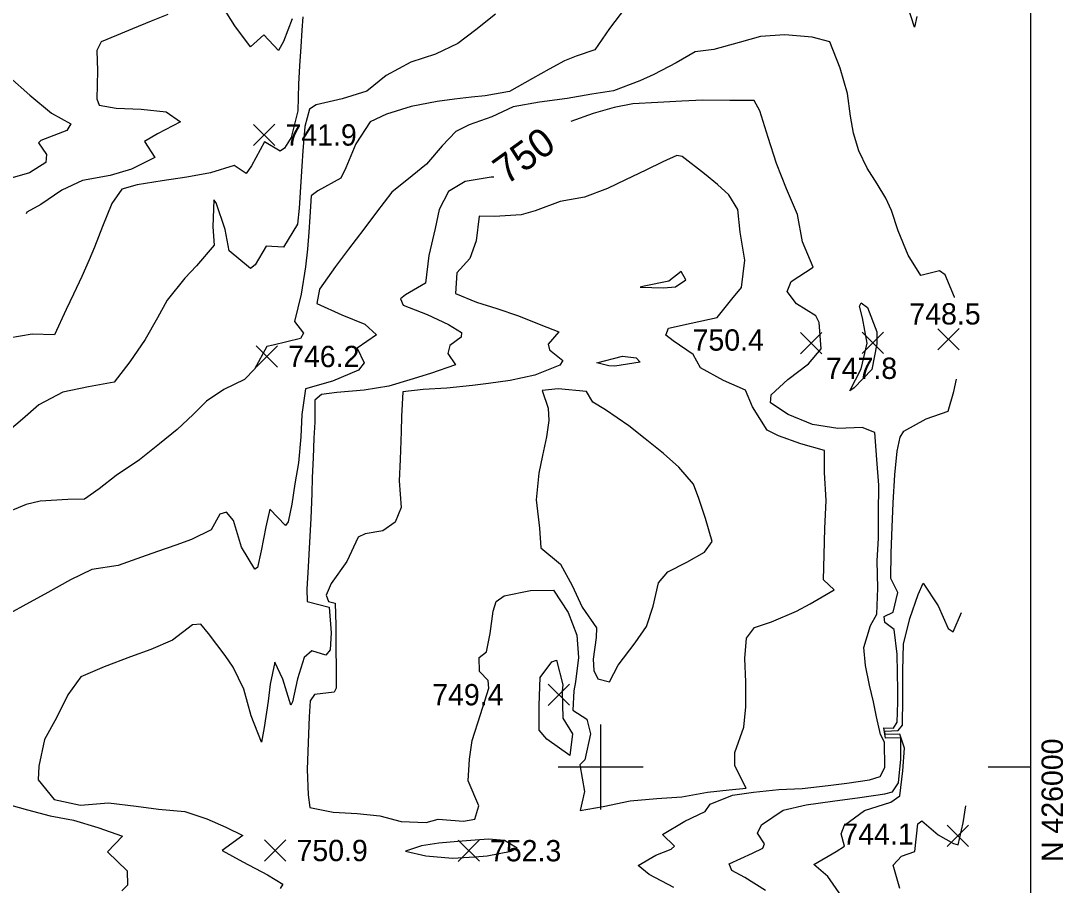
# Model space of a CAD drawing. Extents: x 2566079 to 2571326, y 424054 to 426896.
# Drawn here: x 2570592 to 2571326, y 425917 to 426525 of the extents above; entities that cross this region are included whole.
import ezdxf

# ---------------------------------------------------------------- set-up
doc = ezdxf.new("R2010")
doc.units = 0
for name, color, linetype in [('Contour_ADS_Label_Major', 7, 'Continuous'), ('Contour_ADS_Major', 7, 'Continuous'), ('Contour_ADS_Minor', 7, 'Continuous'), ('Contour_ADS_Spot_Elevation', 7, 'Continuous'), ('Contour_ADS_State_Plane_Border', 7, 'Continuous'), ('Contour_ADS_Tick', 7, 'Continuous')]:
    doc.layers.add(name, color=color, linetype=linetype)

# ---------------------------------------------------------------- blocks, each defined once
blk = doc.blocks.new('S890')
at = {"layer": 'Contour_ADS_Tick'}
for p, q in [((0, -0.5), (0, 0.5)), ((-0.5, 0), (0.5, 0))]:
    blk.add_line(p, q, dxfattribs=at)
blk = doc.blocks.new('S750')
at = {"layer": 'Contour_ADS_Spot_Elevation'}
for p, q in [((-0.5, 0.498), (0.5, -0.498)), ((-0.498, -0.5), (0.498, 0.5))]:
    blk.add_line(p, q, dxfattribs=at)

msp = doc.modelspace()

# ---------------------------------------------------------------- linework, layer by layer
at = {"layer": 'Contour_ADS_Major'}
for points in [[(2570782.76, 426526.65), (2570776.66, 426510.83), (2570773.09, 426504.52), (2570762.75, 426515.5), (2570753.38, 426507.1), (2570742.29, 426521.75), (2570733.83, 426535.09)], [(2570695.09, 426529.67), (2570683.51, 426525.15), (2570670.35, 426519.79), (2570658.94, 426515.1), (2570648.23, 426510.46), (2570645.12, 426504.44), (2570645.77, 426490.18), (2570645.24, 426470.46), (2570646.88, 426465.87), (2570658.86, 426463.87), (2570676.46, 426463.07), (2570694.14, 426461.19), (2570704.09, 426454.15), (2570687.89, 426445.78), (2570678.85, 426440.38), (2570685.97, 426429.12), (2570669.52, 426420.91), (2570654.64, 426416.42), (2570635.19, 426412.92), (2570620.56, 426406.1), (2570605.87, 426395.97), (2570596.02, 426390.51), (2570595.55, 426389.36)], [(2571051.6, 425915.17), (2571034.16, 425924.26), (2571026.36, 425930.55), (2571038.78, 425937.83), (2571049.65, 425942.08), (2571052.04, 425944.33), (2571043.44, 425952.53), (2571059.36, 425961.78), (2571073.47, 425968.77), (2571077.12, 425973.74), (2571092.72, 425980.08), (2571107.51, 425982.25), (2571125.37, 425984.19), (2571141.98, 425984.93), (2571160.28, 425987.07), (2571173.21, 425988.59), (2571189.28, 425990.87), (2571196.76, 425993.24), (2571200.18, 425999.75), (2571199.8, 426017.53), (2571196.99, 426022.9), (2571194.19, 426035.37), (2571192.09, 426045.89), (2571189.29, 426057.52), (2571186.46, 426071.38), (2571185.27, 426084.2), (2571189.98, 426099.65), (2571194.38, 426107.6), (2571195.25, 426125.81), (2571194.64, 426145.24), (2571195.65, 426161.18), (2571195.67, 426178.45), (2571195.74, 426198.39), (2571194.38, 426216.45), (2571193.02, 426235.56), (2571184.03, 426238.94), (2571167.1, 426238.23), (2571149.22, 426241.02), (2571131.92, 426248.06), (2571119.65, 426256.38), (2571120.12, 426261.9), (2571131.85, 426272.85), (2571146.25, 426283.74), (2571155.15, 426294.39), (2571153.88, 426312.95), (2571151.6, 426317.64), (2571137.84, 426326.11), (2571131.4, 426334.71), (2571134.22, 426341.81), (2571149.52, 426351.81), (2571142.22, 426369.66), (2571138.64, 426388.88), (2571130.8, 426407.11), (2571123.91, 426424.93), (2571117.89, 426443.25), (2571112.17, 426462.02), (2571108.16, 426469.25), (2571090.93, 426469.13), (2571071.9, 426469.49), (2571057.12, 426468.79), (2571040.22, 426467.86), (2571022.65, 426466.82), (2571009.53, 426464.24), (2570994.74, 426460.03), (2570978.91, 426454.36)], [(2570924.84, 426415.36), (2570922.78, 426415.18), (2570904.52, 426412.1), (2570892.78, 426405.05), (2570886.27, 426392.38), (2570883.41, 426379.18), (2570879.07, 426360.05), (2570876.58, 426340.56), (2570862.46, 426332.3), (2570858.98, 426329.62), (2570860.99, 426325.22), (2570877.89, 426318.48), (2570892.88, 426311.61), (2570901.88, 426305.82), (2570901.66, 426302.57), (2570893.7, 426296.83), (2570892.41, 426291.05), (2570897.78, 426283.18), (2570880.06, 426277.14), (2570865.66, 426272.48), (2570850.73, 426268.07), (2570833.46, 426265.38), (2570814.22, 426263.71), (2570803.35, 426262.18), (2570798.79, 426258.31), (2570798.63, 426242.7), (2570798.09, 426231.54), (2570797.48, 426217.59), (2570796.92, 426203.79), (2570796.49, 426192.44), (2570795.82, 426174.88), (2570795.02, 426158.38), (2570794.02, 426140.86), (2570793.08, 426125.22), (2570793.23, 426116.5), (2570808.86, 426112.62), (2570810.31, 426094.51), (2570809.4, 426082.49), (2570806.36, 426078.71), (2570796.56, 426081.72), (2570791.2, 426076.99), (2570786.5, 426062.05), (2570783.05, 426045.89), (2570781.82, 426043.62), (2570776.21, 426061.9), (2570770.64, 426073.83), (2570767.22, 426058.39), (2570765.91, 426046.23), (2570763.1, 426027.81), (2570761.07, 426017.59), (2570753.83, 426035.97), (2570748.75, 426054.71), (2570741.21, 426070.2), (2570735.57, 426078.48), (2570723.9, 426094.04), (2570718.33, 426100.55), (2570712.58, 426100.01), (2570698.39, 426089.2), (2570683.29, 426082.68), (2570669.02, 426077.61), (2570650.4, 426070.61), (2570634.04, 426063.51), (2570624.67, 426050.75), (2570616.79, 426034.61), (2570608.34, 426019.25), (2570604.29, 426000.67), (2570603.86, 425990.86), (2570615.19, 425977.08), (2570633.81, 425973.06), (2570653.44, 425974.75), (2570672.98, 425972.49), (2570688.58, 425970.4), (2570707.12, 425968.58), (2570722.75, 425963.42), (2570735.96, 425957.56), (2570748.09, 425951.84), (2570733.53, 425941.11), (2570748.12, 425933.15), (2570765.39, 425923.98), (2570776.12, 425917.51), (2570774.38, 425914.39)]]:
    msp.add_lwpolyline(points, dxfattribs=at)
msp.add_lwpolyline([(2570972.89, 426053.35), (2570973.37, 426034.49), (2570980.26, 426023.42), (2570978.35, 426008.05), (2570962.11, 426019.7), (2570956.59, 426025.91), (2570956.58, 426043.56), (2570957.42, 426063), (2570965.68, 426074.13), (2570968.8, 426075.24), (2570973.35, 426057.9), (2570972.89, 426053.35)], close=True, dxfattribs=at)
at = {"layer": 'Contour_ADS_Minor'}
for points in [[(2571017.39, 426534.66), (2571006.21, 426519.91), (2570995.86, 426504.93), (2570982.72, 426500.39), (2570974.52, 426497.1), (2570963.61, 426491.38), (2570951.97, 426484.7), (2570935.84, 426475.64), (2570918.68, 426472.53), (2570908.95, 426471.55), (2570896.98, 426470.2), (2570884.93, 426468.55), (2570866.62, 426464.95), (2570849.19, 426459.5), (2570837.71, 426454.09), (2570827.61, 426438.69), (2570820.45, 426421.83), (2570817.08, 426414.49), (2570800.88, 426405.59), (2570796.23, 426402.09), (2570795.29, 426387.24), (2570794.54, 426376.57), (2570793.46, 426364.47), (2570792.04, 426352.23), (2570789.19, 426332.82), (2570784.32, 426313.64), (2570790.75, 426305.38), (2570788.58, 426301.68), (2570769.33, 426297.09), (2570764.81, 426295.92), (2570756.2, 426280.08), (2570749.26, 426272.73), (2570734.64, 426265.81), (2570722.43, 426257.59), (2570713.06, 426248.12), (2570701.69, 426237.52), (2570689.42, 426227.55), (2570675.29, 426216.35), (2570658.77, 426205.18), (2570646.92, 426195.88), (2570636.43, 426188.62), (2570624.77, 426188.37), (2570605.41, 426187.26), (2570595.34, 426184.73), (2570577.27, 426177.28)], [(2571222.61, 426528.34), (2571220.86, 426520.88), (2571216.55, 426534.81)], [(2570926, 426530.03), (2570912.13, 426519.08), (2570899.46, 426509.41), (2570883.64, 426501.77), (2570866.31, 426496.16), (2570848.93, 426486.81), (2570835.22, 426475.85), (2570818.07, 426470.32), (2570799.76, 426466.16), (2570794.9, 426463.14), (2570791.64, 426450.89), (2570790.31, 426433.89), (2570789.55, 426422.94), (2570788.79, 426411.99), (2570787.62, 426393.39), (2570786.4, 426382.19), (2570776.72, 426365.95), (2570764.44, 426366.61), (2570756.75, 426353.48), (2570753.48, 426350.86), (2570738.43, 426363.33), (2570735.48, 426378.45), (2570729.27, 426397.09), (2570727.55, 426399.32), (2570726.96, 426380.27), (2570727.79, 426367.3), (2570715.35, 426352.76), (2570707.24, 426344.07), (2570694.77, 426328.63), (2570687.92, 426316.28), (2570679.2, 426301.08), (2570668.38, 426285.35), (2570657.47, 426270.83), (2570639.29, 426267.7), (2570621.21, 426263.9), (2570604.42, 426255.02), (2570592.77, 426244.77), (2570578.85, 426232.9)], [(2570790.31, 426528.19), (2570789.62, 426518.74), (2570788.8, 426506.98), (2570787.91, 426493.69), (2570787.13, 426480.81), (2570786.76, 426461.89), (2570782.07, 426443.27), (2570777.42, 426435.73), (2570774.4, 426433.47), (2570763.3, 426440.07), (2570754.1, 426423.23), (2570750.42, 426417.77), (2570741.96, 426423.38), (2570725.21, 426418.23), (2570708.67, 426415.32), (2570691.11, 426412.76), (2570673.54, 426409.91), (2570662.91, 426406.89), (2570655.7, 426396.62), (2570649.15, 426380.42), (2570643.63, 426365.92), (2570639.8, 426356.94), (2570634.55, 426345.38), (2570628.76, 426332.96), (2570623.65, 426322.06), (2570615.44, 426304.26), (2570599.72, 426304.69), (2570583.2, 426301.98)], [(2571249.23, 426330.42), (2571249.16, 426330.65), (2571242.57, 426346.48), (2571238.53, 426349.27), (2571225.32, 426346.03), (2571216.53, 426360.38), (2571209.38, 426377.55), (2571204.84, 426391.72), (2571200.76, 426400.41), (2571194.63, 426410.45), (2571187.71, 426421.66), (2571181.7, 426433.77), (2571177.9, 426446.32), (2571175.87, 426458.09), (2571173.82, 426474.17), (2571168.52, 426492.04), (2571161.43, 426510.64), (2571148.84, 426513.76), (2571129.75, 426515.5), (2571112.49, 426514.39), (2571097.43, 426510.09), (2571079.6, 426505.11), (2571066.63, 426503.57), (2571053.15, 426495.74), (2571037.42, 426487.63), (2571027.65, 426482.97), (2571008.95, 426476.03), (2570993.73, 426473.62), (2570976.33, 426470.67), (2570956.8, 426468.02), (2570938.28, 426464.82), (2570923.29, 426457.82), (2570907.48, 426452.16), (2570898, 426447.35), (2570888.38, 426437.27), (2570877.34, 426424.49), (2570867.22, 426416.22), (2570852.89, 426404.62), (2570842.17, 426390.68), (2570833.11, 426378.71), (2570822.51, 426364.61), (2570813.18, 426352.24), (2570801.91, 426336.42), (2570800.21, 426326.3), (2570817.81, 426318.38), (2570833.93, 426311.85), (2570842.12, 426304.25), (2570828.5, 426294.83), (2570833.43, 426284.64), (2570829.56, 426279.34), (2570811.2, 426271.67), (2570792.17, 426266.23), (2570789.6, 426248.05), (2570788.96, 426232.36), (2570787.22, 426214.19), (2570784.69, 426199.43), (2570782.41, 426185.05), (2570780.02, 426172.55), (2570778.01, 426170.04), (2570767.01, 426181.49), (2570764.27, 426169.02), (2570760.87, 426152.26), (2570758.28, 426140.56), (2570756.51, 426139.24), (2570747.14, 426154.75), (2570741.37, 426173.45), (2570736.51, 426179.44), (2570731.92, 426178.04), (2570725.68, 426166.88), (2570711.96, 426160.07), (2570700.76, 426156.15), (2570687.96, 426151.73), (2570676.55, 426147.72), (2570660.16, 426141.82), (2570641.61, 426138.95), (2570626.63, 426131.78), (2570618.68, 426127.26), (2570608.57, 426121.73), (2570597.83, 426115.92), (2570581.64, 426106.79)], [(2570583.62, 426485.61), (2570597.95, 426473.04), (2570613.36, 426460.35), (2570627, 426452.72), (2570624.03, 426448), (2570605.71, 426441.02), (2570604.17, 426439.32), (2570609.67, 426431.09), (2570609.2, 426425.68), (2570597.82, 426418.23), (2570585.65, 426414.87)], [(2570980.97, 426053.57), (2570980.31, 426040.07), (2570990.3, 426033.77), (2570992.74, 426023.32), (2570988.79, 426004.93), (2570985.31, 426001.41), (2570988.65, 425982.64), (2570985.61, 425969.3), (2571001.69, 425972.15), (2571020.81, 425976.18), (2571039.47, 425977.77), (2571057.19, 425979.01), (2571075.18, 425982.21), (2571090.42, 425983.93), (2571102.43, 425985), (2571094.39, 426000.92), (2571094.52, 426010.1), (2571100.78, 426028.13), (2571102.21, 426042.24), (2571102.2, 426059.88), (2571101.52, 426076.47), (2571102.72, 426090.69), (2571108.35, 426098.26), (2571120.28, 426102.26), (2571137.99, 426109.6), (2571147.46, 426114.78), (2571164.36, 426124.84), (2571156.84, 426131.68), (2571157.42, 426149.46), (2571157.94, 426167.97), (2571158.77, 426187.66), (2571157.55, 426207.31), (2571157.58, 426222.82), (2571140.87, 426227.46), (2571125.18, 426233.1), (2571117.22, 426237.06), (2571106.96, 426253.55), (2571102.03, 426265.3), (2571086.52, 426272.18), (2571070.21, 426281.06), (2571065.02, 426290.46), (2571051.09, 426300.11), (2571045.98, 426303.95), (2571047.69, 426308.83), (2571063.61, 426312.56), (2571082.02, 426316.43), (2571092.35, 426329.41), (2571099.08, 426337.66), (2571101.4, 426356.88), (2571098.15, 426376.57), (2571096.63, 426392.52), (2571090.32, 426402.78), (2571082.35, 426410.03), (2571072.98, 426417.53), (2571057.4, 426429.69), (2571053.51, 426430.5), (2571043.76, 426426.03), (2571031.71, 426420.23), (2571017.46, 426413.34), (2571004.9, 426407.32), (2570988.63, 426401.27), (2570971.35, 426398.11), (2570953.9, 426391.52), (2570944.11, 426388.79), (2570925.23, 426387.65), (2570914.47, 426387.68), (2570912.28, 426370.51), (2570907.93, 426357.93), (2570898.8, 426347.96), (2570897.71, 426333.41), (2570912.47, 426327.32), (2570926.84, 426322.8), (2570942.19, 426317.57), (2570957.9, 426311.27), (2570970.47, 426306.3), (2570963.06, 426297.7), (2570963.91, 426293.69), (2570973.24, 426286.19), (2570971.27, 426282.86), (2570953.73, 426275.9), (2570936.23, 426272.01), (2570921.01, 426270.04), (2570909.71, 426268.64), (2570891.57, 426266.8), (2570875.03, 426265.8), (2570860.7, 426264.06), (2570859.66, 426246.64), (2570859.48, 426236.3), (2570858.72, 426216.41), (2570858.14, 426201.56), (2570859.54, 426182.65), (2570855.35, 426172.26), (2570846.53, 426166.3), (2570834.24, 426164.09), (2570829.14, 426161.8), (2570821.27, 426144.68), (2570810.2, 426129.29), (2570806.71, 426120.96), (2570808.31, 426116.45), (2570812.98, 426115.31), (2570813.46, 426099.8)], [(2571229.22, 426245.19), (2571244.77, 426250.62), (2571248.58, 426264.29), (2571250.5, 426273.03)], [(2571116.02, 425913.13), (2571101.47, 425922.15), (2571092.35, 425927.09), (2571090.39, 425931.75), (2571106.8, 425939.45), (2571114.09, 425942.96), (2571115.4, 425946.01), (2571110.5, 425953.45), (2571113.29, 425959.25), (2571128.38, 425969.66), (2571144.62, 425973.27), (2571163.29, 425975.88), (2571182.43, 425978.44), (2571200.09, 425981.11), (2571205.57, 425982.6), (2571209.78, 425988.79), (2571211.32, 426005.48), (2571211.38, 426020.49), (2571200.49, 426020.41), (2571199.47, 426027.47), (2571206.24, 426027.35), (2571208.74, 426031.52), (2571209.15, 426045.65), (2571209.12, 426054.15), (2571209.09, 426066.24), (2571208.84, 426079.4), (2571206.63, 426096.8), (2571200.06, 426101.7), (2571199.59, 426105.95), (2571206.05, 426108.98), (2571209.29, 426122.76), (2571204.28, 426132.64), (2571204.53, 426150.79), (2571205.15, 426168.89), (2571205.96, 426186.01), (2571207.18, 426205.65), (2571208.84, 426222.4), (2571210.94, 426232.22), (2571213.39, 426236.54), (2571229.22, 426245.19)], [(2571169.6, 425909.12), (2571159.94, 425923), (2571149.99, 425931.28), (2571165.83, 425940.6), (2571171.69, 425944.32), (2571169.35, 425952.85), (2571171.62, 425959.06), (2571185.7, 425969.49), (2571204.23, 425975.14), (2571210.61, 425979.73), (2571212.87, 425997.4), (2571213.89, 426013.17), (2571210.56, 426023.16), (2571200.34, 426022.77), (2571200.1, 426025.16), (2571209.38, 426025.79), (2571212.5, 426029.49), (2571212.7, 426048.57), (2571212.76, 426067.99), (2571213.32, 426086.56), (2571217.68, 426104.61), (2571223.57, 426121.47), (2571227.16, 426129.33), (2571237.53, 426113.43), (2571244.66, 426097.6), (2571248.12, 426095.13), (2571254.16, 426108.85)], [(2570813.46, 426099.8), (2570813.51, 426085.85), (2570813.75, 426067.24), (2570813.74, 426055.44), (2570812.23, 426052.65), (2570798.51, 426051.05), (2570795.31, 426046.66), (2570794.72, 426035.37), (2570793.93, 426017.34), (2570793.27, 425998.21), (2570793.96, 425980.39), (2570795.19, 425971.54), (2570811.71, 425968.14), (2570828.59, 425967.37), (2570844.49, 425965.53), (2570859.4, 425961.6), (2570877.22, 425960.87), (2570885.56, 425963.37), (2570903.36, 425961.77), (2570911.28, 425963.22), (2570914.18, 425972.62), (2570906.75, 425990.17), (2570907.63, 426005.4), (2570909.55, 426018.58), (2570915.45, 426036.93), (2570921.25, 426055.43), (2570920.77, 426060.88), (2570914.67, 426067.25), (2570914.32, 426077.15), (2570919.56, 426081.17), (2570922.11, 426093.88), (2570924.33, 426109.63), (2570926.51, 426116.6), (2570932.05, 426120.5), (2570950.63, 426124.21), (2570966.8, 426124.41), (2570977.07, 426108.82), (2570983.22, 426092.91), (2570984.34, 426077), (2570982.22, 426059.92), (2570980.97, 426053.57), (2570980.97, 426053.57)], [(2570578.67, 425974.69), (2570596.34, 425969.84), (2570612.26, 425965.68), (2570628.87, 425962.64), (2570645.86, 425957.34), (2570663.33, 425951.38), (2570652.71, 425940.3)], [(2571210.63, 425914.52), (2571206.01, 425930.8), (2571211.89, 425937.13), (2571221.19, 425940.41), (2571223.31, 425960.03), (2571226.02, 425962.14), (2571237.58, 425952.14), (2571248.48, 425946.04), (2571251.63, 425945.2), (2571255.12, 425960.6), (2571257.19, 425972.74)], [(2570652.71, 425940.3), (2570666.49, 425926.83), (2570666.74, 425916.92), (2570662.82, 425912.83)]]:
    msp.add_lwpolyline(points, dxfattribs=at)
for points in [[(2571059.88, 426342.87), (2571056.64, 426348.74), (2571047.89, 426342.05), (2571030.53, 426338.49), (2571027.77, 426337.71), (2571044.3, 426337.36), (2571052.64, 426337.93), (2571059.88, 426342.87)], [(2571194.56, 426297.89), (2571190.93, 426279.92), (2571178.44, 426266.85), (2571175.43, 426264.91), (2571183.33, 426280.23), (2571187.69, 426298.47), (2571184.32, 426316.16), (2571182.17, 426324.38), (2571183.34, 426326.69), (2571187.8, 426323.6), (2571194.46, 426306.34), (2571194.56, 426297.89)], [(2571005.68, 426282.46), (2570997.26, 426284.62), (2571015.26, 426289.2), (2571024.93, 426288.12), (2571027.81, 426284.97), (2571010.07, 426282.08), (2571005.68, 426282.46)], [(2570996.8, 426091.28), (2570994.61, 426075.9), (2570995.17, 426067.89), (2570997.92, 426062), (2571006.12, 426059.96), (2571012.22, 426071.61), (2571024.2, 426087.39), (2571032.28, 426098.86), (2571036.94, 426113.24), (2571040.71, 426129.66), (2571047.23, 426137.4), (2571060.7, 426144.28), (2571073.03, 426151.28), (2571078.47, 426158.75), (2571073.85, 426174.9), (2571069.2, 426189.06), (2571065.33, 426199.05), (2571055.11, 426211.15), (2571044.19, 426220.67), (2571031.41, 426231.08), (2571019.9, 426240.08), (2571003.42, 426251.39), (2570994.43, 426256.89), (2570989.99, 426264.43), (2570970.16, 426266.2), (2570958.86, 426265.13), (2570963.1, 426252.72), (2570963.49, 426244), (2570961.82, 426232.37), (2570959, 426219.36), (2570956.35, 426206.92), (2570954.59, 426188.05), (2570956.86, 426168.2), (2570957.78, 426154.4), (2570971.6, 426142.71), (2570979.9, 426127.76), (2570987, 426112.42), (2570997.12, 426097.98), (2570996.8, 426091.28)], [(2570919.96, 425937.56), (2570936.96, 425940.74), (2570941.23, 425942.78), (2570932.24, 425948.31), (2570921.09, 425949.1), (2570911.66, 425948.51), (2570899.36, 425947.57), (2570886.07, 425946.26), (2570873.82, 425944.57), (2570862.55, 425940.71), (2570876.93, 425937.39), (2570895.54, 425935.72), (2570911.46, 425936.66), (2570919.96, 425937.56)]]:
    msp.add_lwpolyline(points, close=True, dxfattribs=at)
at = {"layer": 'Contour_ADS_State_Plane_Border'}
msp.add_line((2571272.93, 426000), (2571302.93, 426000), dxfattribs=at)
msp.add_lwpolyline([(2566079.33, 424077.11), (2571302.93, 424077.11), (2571302.93, 426873.74), (2566079.33, 426873.74), (2566079.33, 424077.11)], close=True, dxfattribs=at)

# ---------------------------------------------------------------- block references
at = {"layer": 'Contour_ADS_Spot_Elevation', "xscale": 15, "yscale": 15}
for p in [(2570763.03, 426444.96), (2571148.21, 426298.37), (2571191.67, 426298.61), (2571244.88, 426301.11), (2570764.9, 426289.02), (2570970.47, 426050.89), (2571251.45, 425951.6), (2570770.82, 425941.22), (2570907.07, 425941.07)]:
    msp.add_blockref('S750', p, dxfattribs=at)
at = {"layer": 'Contour_ADS_Tick', "xscale": 60, "yscale": 60}
msp.add_blockref('S890', (2571000, 426000), dxfattribs=at)

# ---------------------------------------------------------------- texts
at = {"layer": 'Contour_ADS_Label_Major'}
msp.add_text('750', height=20, rotation=35.80264, dxfattribs=at).set_placement((2570933.62, 426409.36))
at = {"layer": 'Contour_ADS_Spot_Elevation'}
for s, p in [('741.9', (2570778.03, 426437.46)), ('748.5', (2571217.35, 426311.52)), ('750.4', (2571064.71, 426293.11)), ('746.2', (2570779.9, 426281.52)), ('747.8', (2571158.54, 426273.2)), ('749.4', (2570881.38, 426043.39)), ('744.1', (2571170.19, 425945.22)), ('750.9', (2570785.82, 425933.72)), ('752.3', (2570922.07, 425933.57))]:
    msp.add_text(s, height=15, dxfattribs=at).set_placement(p)
at = {"layer": 'Contour_ADS_State_Plane_Border'}
msp.add_text(' N 426000', height=15, rotation=90, dxfattribs=at).set_placement((2571325.43, 425927.5))

doc.saveas('drawing.dxf')
